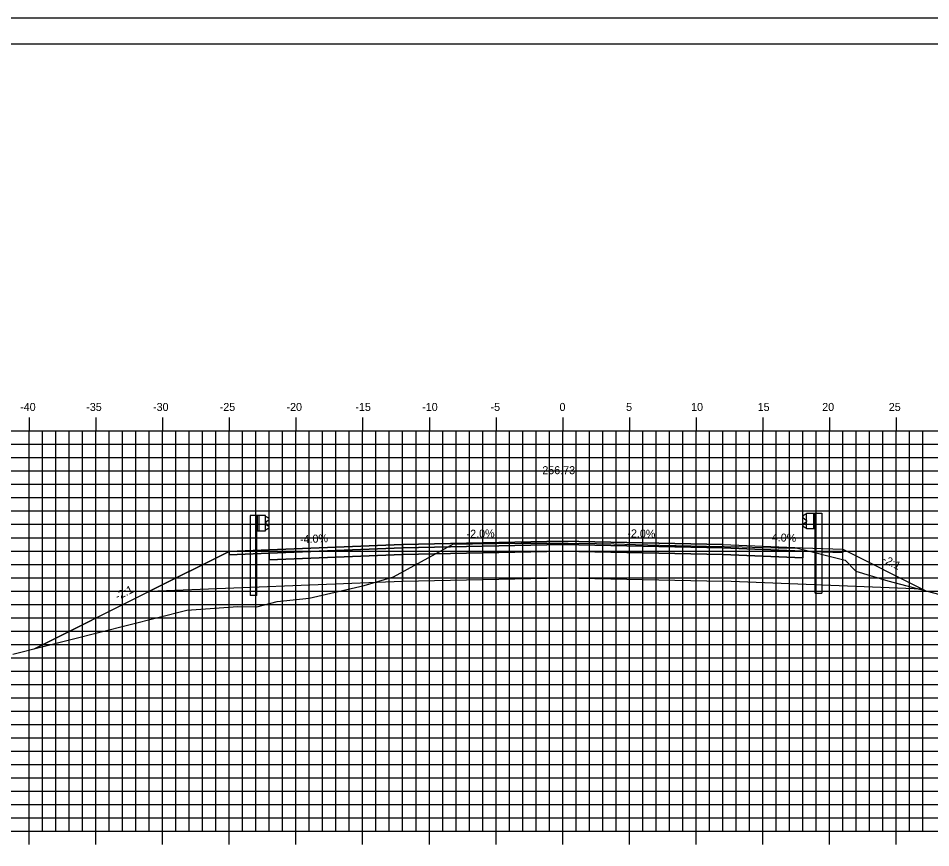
# Model space of a CAD drawing. Extents: x -22 to 1480, y -1511 to 8.
# Drawn here: x 241.9 to 310.3, y -136.7 to -74.5 of the extents above; entities that cross this region are included whole.
import ezdxf

# ---------------------------------------------------------------- set-up
doc = ezdxf.new("R2010")
doc.units = 0
for name, color, linetype in [('ANNOTATION', 7, 'Continuous'), ('BORDER', 7, 'Continuous'), ('D_Guardrail_Beam_Lt', 7, 'Continuous'), ('D_Guardrail_Beam_Rt', 7, 'Continuous'), ('D_Roadway_Centerline', 7, 'Continuous'), ('D_Roadway_Centerline_Text', 7, 'Continuous'), ('D_Roadway_Edge_Shoulder', 7, 'Continuous'), ('D_Roadway_Edge_TW', 7, 'Continuous'), ('D_Roadway_Pavement', 7, 'Continuous'), ('D_Roadway_SlopeLines', 7, 'Continuous'), ('D_Roadway_SubGrade', 7, 'Continuous'), ('H_V ANNOTATION', 7, 'Continuous'), ('MAJOR', 7, 'Continuous'), ('MINOR', 7, 'Continuous'), ('PLOT BOUNDARY', 7, 'Continuous'), ('S_Roadway_Centerline', 7, 'Continuous')]:
    doc.layers.add(name, color=color, linetype=linetype)

msp = doc.modelspace()

# ---------------------------------------------------------------- linework, layer by layer
at = {"layer": 'BORDER'}
msp.add_line((367.696, -76.466), (207.696, -76.466), dxfattribs=at)
at = {"layer": 'D_Guardrail_Beam_Lt'}
for p, q in [((300.877, -111.739), (300.733, -111.839)), ((300.733, -111.982), (300.928, -112.119)), ((300.967, -111.718), (300.892, -111.733)), ((300.962, -112.183), (300.962, -112.253)), ((300.967, -111.635), (301.654, -111.635)), ((300.967, -112.801), (300.967, -111.635)), ((301.487, -111.635), (301.487, -112.801)), ((301.592, -111.635), (301.592, -112.801)), ((301.654, -111.635), (302.125, -111.635)), ((301.654, -111.635), (301.654, -112.801)), ((302.125, -111.635), (302.125, -117.635)), ((300.928, -112.318), (300.733, -112.454)), ((300.733, -112.597), (300.877, -112.697)), ((300.892, -112.703), (300.967, -112.718)), ((301.654, -112.801), (300.967, -112.801)), ((301.633, -117.635), (301.633, -112.801)), ((301.633, -117.635), (302.125, -117.635))]:
    msp.add_line(p, q, dxfattribs=at)
for centre, major_axis, start_param, end_param in [((300.783, -111.911), (-0.0877, 0), 5.323254, 7.243116), ((300.9, -111.773), (-0.0417, 0), 4.907132, 5.323254), ((300.883, -112.183), (0.0789, 0), 0, 0.959931), ((300.783, -112.525), (-0.0877, 0), 5.323254, 7.243116), ((300.9, -112.663), (-0.0417, 0), 0.959931, 1.376053), ((300.883, -112.253), (0.0789, 0), 5.323254, 6.283185)]:
    msp.add_ellipse(centre, major_axis=major_axis, ratio=0.995501, start_param=start_param, end_param=end_param, dxfattribs=at)
at = {"layer": 'D_Guardrail_Beam_Rt'}
for p, q in [((259.267, -111.795), (259.267, -117.795)), ((259.737, -111.795), (259.267, -111.795)), ((260.425, -111.795), (259.737, -111.795)), ((259.737, -111.795), (259.737, -112.961)), ((259.8, -111.795), (259.8, -112.961)), ((259.904, -111.795), (259.904, -112.961)), ((260.425, -112.961), (260.425, -111.795)), ((260.425, -111.878), (260.499, -111.893)), ((260.658, -112.142), (260.463, -112.279)), ((260.515, -111.899), (260.658, -111.999)), ((260.499, -112.863), (260.425, -112.878)), ((260.429, -112.343), (260.429, -112.413)), ((260.463, -112.478), (260.658, -112.614)), ((260.658, -112.757), (260.515, -112.857)), ((259.737, -112.961), (260.425, -112.961)), ((259.758, -117.795), (259.758, -112.961)), ((259.758, -117.795), (259.267, -117.795))]:
    msp.add_line(p, q, dxfattribs=at)
for centre, major_axis, start_param, end_param in [((260.491, -111.933), (0.0417, 0), 0.959931, 1.376053), ((260.608, -112.071), (0.0877, 0), 5.323254, 7.243116), ((260.508, -112.343), (-0.0789, 0), 5.323254, 6.283185), ((260.508, -112.413), (-0.0789, 0), 6.283185, 7.243116), ((260.491, -112.823), (0.0417, 0), 4.907132, 5.323254), ((260.608, -112.685), (0.0877, 0), 5.323254, 7.243116)]:
    msp.add_ellipse(centre, major_axis=major_axis, ratio=0.995501, start_param=start_param, end_param=end_param, dxfattribs=at)
at = {"layer": 'D_Roadway_Centerline'}
msp.add_lwpolyline([(243.098, -121.797), (251.717, -117.487), (257.696, -114.498), (260.696, -114.378), (270.696, -113.978), (282.696, -113.738), (294.696, -113.978), (300.696, -114.218), (303.696, -114.338), (309.674, -117.327), (309.879, -117.43)], dxfattribs=at)
at = {"layer": 'D_Roadway_Edge_Shoulder'}
for points in [[(270.696, -113.978), (260.696, -114.378), (260.696, -114.378), (257.696, -114.498), (257.696, -114.748), (260.696, -114.628), (260.696, -114.628), (270.696, -114.228)], [(294.696, -113.978), (300.696, -114.218), (300.696, -114.218), (303.696, -114.338), (303.696, -114.588), (300.696, -114.468), (300.696, -114.468), (294.696, -114.228)]]:
    msp.add_lwpolyline(points, close=True, dxfattribs=at)
at = {"layer": 'D_Roadway_Edge_TW'}
msp.add_lwpolyline([(294.696, -114.228), (294.696, -113.978), (282.696, -113.738), (270.696, -113.978), (270.696, -114.228), (282.696, -113.988)], close=True, dxfattribs=at)
at = {"layer": 'D_Roadway_Pavement'}
for points in [[(270.696, -114.228), (260.696, -114.628), (260.696, -114.628), (260.696, -115.128), (270.696, -114.728), (270.696, -114.228)], [(294.696, -114.228), (300.696, -114.468), (300.696, -114.468), (300.696, -114.968), (294.696, -114.728), (294.696, -114.228)]]:
    msp.add_lwpolyline(points, dxfattribs=at)
msp.add_lwpolyline([(294.696, -114.728), (294.696, -114.228), (282.696, -113.988), (270.696, -114.228), (270.696, -114.728), (282.696, -114.488)], close=True, dxfattribs=at)
at = {"layer": 'D_Roadway_SlopeLines'}
for points in [[(257.696, -114.498), (243.098, -121.797)], [(303.696, -114.338), (309.879, -117.43)]]:
    msp.add_lwpolyline(points, dxfattribs=at)
at = {"layer": 'D_Roadway_SubGrade'}
for points in [[(270.696, -114.728), (260.696, -115.128), (260.696, -114.628), (257.696, -114.748), (257.696, -114.498), (251.717, -117.487), (270.696, -116.728)], [(294.696, -116.728), (294.696, -114.728), (282.696, -114.488), (270.696, -114.728), (270.696, -116.728), (282.696, -116.488)], [(294.696, -114.728), (300.696, -114.968), (300.696, -114.468), (303.696, -114.588), (303.696, -114.338), (309.674, -117.327), (294.696, -116.728)]]:
    msp.add_lwpolyline(points, close=True, dxfattribs=at)
at = {"layer": 'MAJOR'}
for p, q in [((242.696, -104.464), (242.696, -105.466)), ((247.696, -104.464), (247.696, -105.466)), ((252.696, -104.464), (252.696, -105.466)), ((257.696, -104.464), (257.696, -105.466)), ((262.696, -104.464), (262.696, -105.466)), ((267.696, -104.464), (267.696, -105.466)), ((272.696, -104.464), (272.696, -105.466)), ((277.696, -104.464), (277.696, -105.466)), ((282.696, -104.464), (282.696, -105.466)), ((287.696, -104.464), (287.696, -105.466)), ((292.696, -104.464), (292.696, -105.466)), ((297.696, -104.464), (297.696, -105.466)), ((302.696, -104.464), (302.696, -105.466)), ((307.696, -104.464), (307.696, -105.466)), ((212.696, -105.466), (352.696, -105.466)), ((212.696, -105.466), (352.696, -105.466)), ((242.696, -135.466), (242.696, -105.466)), ((247.696, -135.466), (247.696, -105.466)), ((252.696, -135.466), (252.696, -105.466)), ((257.696, -135.466), (257.696, -105.466)), ((262.696, -135.466), (262.696, -105.466)), ((267.696, -135.466), (267.696, -105.466)), ((272.696, -135.466), (272.696, -105.466)), ((277.696, -135.466), (277.696, -105.466)), ((282.696, -135.466), (282.696, -105.466)), ((287.696, -135.466), (287.696, -105.466)), ((292.696, -135.466), (292.696, -105.466)), ((297.696, -135.466), (297.696, -105.466)), ((302.696, -135.466), (302.696, -105.466)), ((307.696, -135.466), (307.696, -105.466)), ((212.696, -110.466), (352.696, -110.466)), ((212.696, -115.466), (352.696, -115.466)), ((212.696, -120.466), (352.696, -120.466)), ((212.696, -125.466), (352.696, -125.466)), ((212.696, -130.466), (352.696, -130.466)), ((212.696, -135.466), (352.696, -135.466)), ((212.696, -135.466), (352.696, -135.466)), ((242.696, -136.468), (242.696, -135.466)), ((247.696, -136.468), (247.696, -135.466)), ((252.696, -136.468), (252.696, -135.466)), ((257.696, -136.468), (257.696, -135.466)), ((262.696, -136.468), (262.696, -135.466)), ((267.696, -136.468), (267.696, -135.466)), ((272.696, -136.468), (272.696, -135.466)), ((277.696, -136.468), (277.696, -135.466)), ((282.696, -136.468), (282.696, -135.466)), ((287.696, -136.468), (287.696, -135.466)), ((292.696, -136.468), (292.696, -135.466)), ((297.696, -136.468), (297.696, -135.466)), ((302.696, -136.468), (302.696, -135.466)), ((307.696, -136.468), (307.696, -135.466))]:
    msp.add_line(p, q, dxfattribs=at)
at = {"layer": 'MINOR'}
for p, q in [((243.696, -135.466), (243.696, -105.466)), ((244.696, -135.466), (244.696, -105.466)), ((245.696, -135.466), (245.696, -105.466)), ((246.696, -135.466), (246.696, -105.466)), ((248.696, -135.466), (248.696, -105.466)), ((249.696, -135.466), (249.696, -105.466)), ((250.696, -135.466), (250.696, -105.466)), ((251.696, -135.466), (251.696, -105.466)), ((253.696, -135.466), (253.696, -105.466)), ((254.696, -135.466), (254.696, -105.466)), ((255.696, -135.466), (255.696, -105.466)), ((256.696, -135.466), (256.696, -105.466)), ((258.696, -135.466), (258.696, -105.466)), ((259.696, -135.466), (259.696, -105.466)), ((260.696, -135.466), (260.696, -105.466)), ((261.696, -135.466), (261.696, -105.466)), ((263.696, -135.466), (263.696, -105.466)), ((264.696, -135.466), (264.696, -105.466)), ((265.696, -135.466), (265.696, -105.466)), ((266.696, -135.466), (266.696, -105.466)), ((268.696, -135.466), (268.696, -105.466)), ((269.696, -135.466), (269.696, -105.466)), ((270.696, -135.466), (270.696, -105.466)), ((271.696, -135.466), (271.696, -105.466)), ((273.696, -135.466), (273.696, -105.466)), ((274.696, -135.466), (274.696, -105.466)), ((275.696, -135.466), (275.696, -105.466)), ((276.696, -135.466), (276.696, -105.466)), ((278.696, -135.466), (278.696, -105.466)), ((279.696, -135.466), (279.696, -105.466)), ((280.696, -135.466), (280.696, -105.466)), ((281.696, -135.466), (281.696, -105.466)), ((283.696, -135.466), (283.696, -105.466)), ((284.696, -135.466), (284.696, -105.466)), ((285.696, -135.466), (285.696, -105.466)), ((286.696, -135.466), (286.696, -105.466)), ((288.696, -135.466), (288.696, -105.466)), ((289.696, -135.466), (289.696, -105.466)), ((290.696, -135.466), (290.696, -105.466)), ((291.696, -135.466), (291.696, -105.466)), ((293.696, -135.466), (293.696, -105.466)), ((294.696, -135.466), (294.696, -105.466)), ((295.696, -135.466), (295.696, -105.466)), ((296.696, -135.466), (296.696, -105.466)), ((298.696, -135.466), (298.696, -105.466)), ((299.696, -135.466), (299.696, -105.466)), ((300.696, -135.466), (300.696, -105.466)), ((301.696, -135.466), (301.696, -105.466)), ((303.696, -135.466), (303.696, -105.466)), ((304.696, -135.466), (304.696, -105.466)), ((305.696, -135.466), (305.696, -105.466)), ((306.696, -135.466), (306.696, -105.466)), ((308.696, -135.466), (308.696, -105.466)), ((309.696, -135.466), (309.696, -105.466)), ((212.696, -106.466), (352.696, -106.466)), ((212.696, -107.466), (352.696, -107.466)), ((212.696, -108.466), (352.696, -108.466)), ((212.696, -109.466), (352.696, -109.466)), ((212.696, -111.466), (352.696, -111.466)), ((212.696, -112.466), (352.696, -112.466)), ((212.696, -113.466), (352.696, -113.466)), ((212.696, -114.466), (352.696, -114.466)), ((212.696, -116.466), (352.696, -116.466)), ((212.696, -117.466), (352.696, -117.466)), ((212.696, -118.466), (352.696, -118.466)), ((212.696, -119.466), (352.696, -119.466)), ((212.696, -121.466), (352.696, -121.466)), ((212.696, -122.466), (352.696, -122.466)), ((212.696, -123.466), (352.696, -123.466)), ((212.696, -124.466), (352.696, -124.466)), ((212.696, -126.466), (352.696, -126.466)), ((212.696, -127.466), (352.696, -127.466)), ((212.696, -128.466), (352.696, -128.466)), ((212.696, -129.466), (352.696, -129.466)), ((212.696, -131.466), (352.696, -131.466)), ((212.696, -132.466), (352.696, -132.466)), ((212.696, -133.466), (352.696, -133.466)), ((212.696, -134.466), (352.696, -134.466))]:
    msp.add_line(p, q, dxfattribs=at)
at = {"layer": 'PLOT BOUNDARY'}
msp.add_lwpolyline([(199.603, -184.525), (369.603, -184.525), (369.603, -74.525), (199.603, -74.525)], close=True, dxfattribs=at)
at = {"layer": 'S_Roadway_Centerline'}
msp.add_lwpolyline([(241.466, -122.211), (254.506, -118.902), (258.333, -118.617), (259.767, -118.657), (261.277, -118.263), (263.686, -117.989), (267.8, -117.057), (270.016, -116.405), (273.17, -114.676), (274.512, -113.93), (275.931, -113.92), (279.584, -113.888), (281.75, -113.872), (283.099, -113.884), (285.231, -113.908), (286.519, -113.939), (288.148, -113.975), (290.898, -114.049), (291.197, -114.056), (293.464, -114.1), (296.154, -114.161), (297.662, -114.199), (298.841, -114.224), (300.193, -114.225), (303.877, -115.152), (304.683, -115.983), (307.068, -116.691), (343.873, -126.363)], dxfattribs=at)

# ---------------------------------------------------------------- texts
at = {"layer": 'ANNOTATION'}
for s, rotation, p in [('-2.0%', 1.14576, (275.499, -113.482)), ('-2.0%', 358.85424, (287.539, -113.435)), ('-4.0%', 2.29061, (263.012, -113.885)), ('-4.0%', 357.70939, (298.092, -113.713)), ('-2:1', 333.43495, (306.611, -115.277)), ('-2:1', 26.56505, (249.326, -118.165))]:
    msp.add_text(s, height=0.6, rotation=rotation, dxfattribs=at).set_placement(p)
at = {"layer": 'D_Roadway_Centerline'}
for s, p in [('C', (282.69, -113.738)), ('L', (282.696, -113.745))]:
    msp.add_text(s, height=0.0146, dxfattribs=at).set_placement(p)
at = {"layer": 'D_Roadway_Centerline_Text'}
msp.add_text('256.73', height=0.6, dxfattribs=at).set_placement((281.168, -108.706))
at = {"layer": 'H_V ANNOTATION'}
for s, p in [('-40', (242.021, -103.966)), ('-35', (246.976, -103.966)), ('-30', (251.984, -103.966)), ('-25', (256.981, -103.966)), ('-20', (261.989, -103.966)), ('-15', (267.153, -103.966)), ('-10', (272.161, -103.966)), ('-5', (277.286, -103.966)), ('0', (282.455, -103.966)), ('5', (287.447, -103.966)), ('10', (292.321, -103.966)), ('15', (297.313, -103.966)), ('20', (302.15, -103.966)), ('25', (307.142, -103.966))]:
    msp.add_text(s, height=0.6, dxfattribs=at).set_placement(p)

doc.saveas('drawing.dxf')
